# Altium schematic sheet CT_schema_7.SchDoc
size 405 x 220 mm
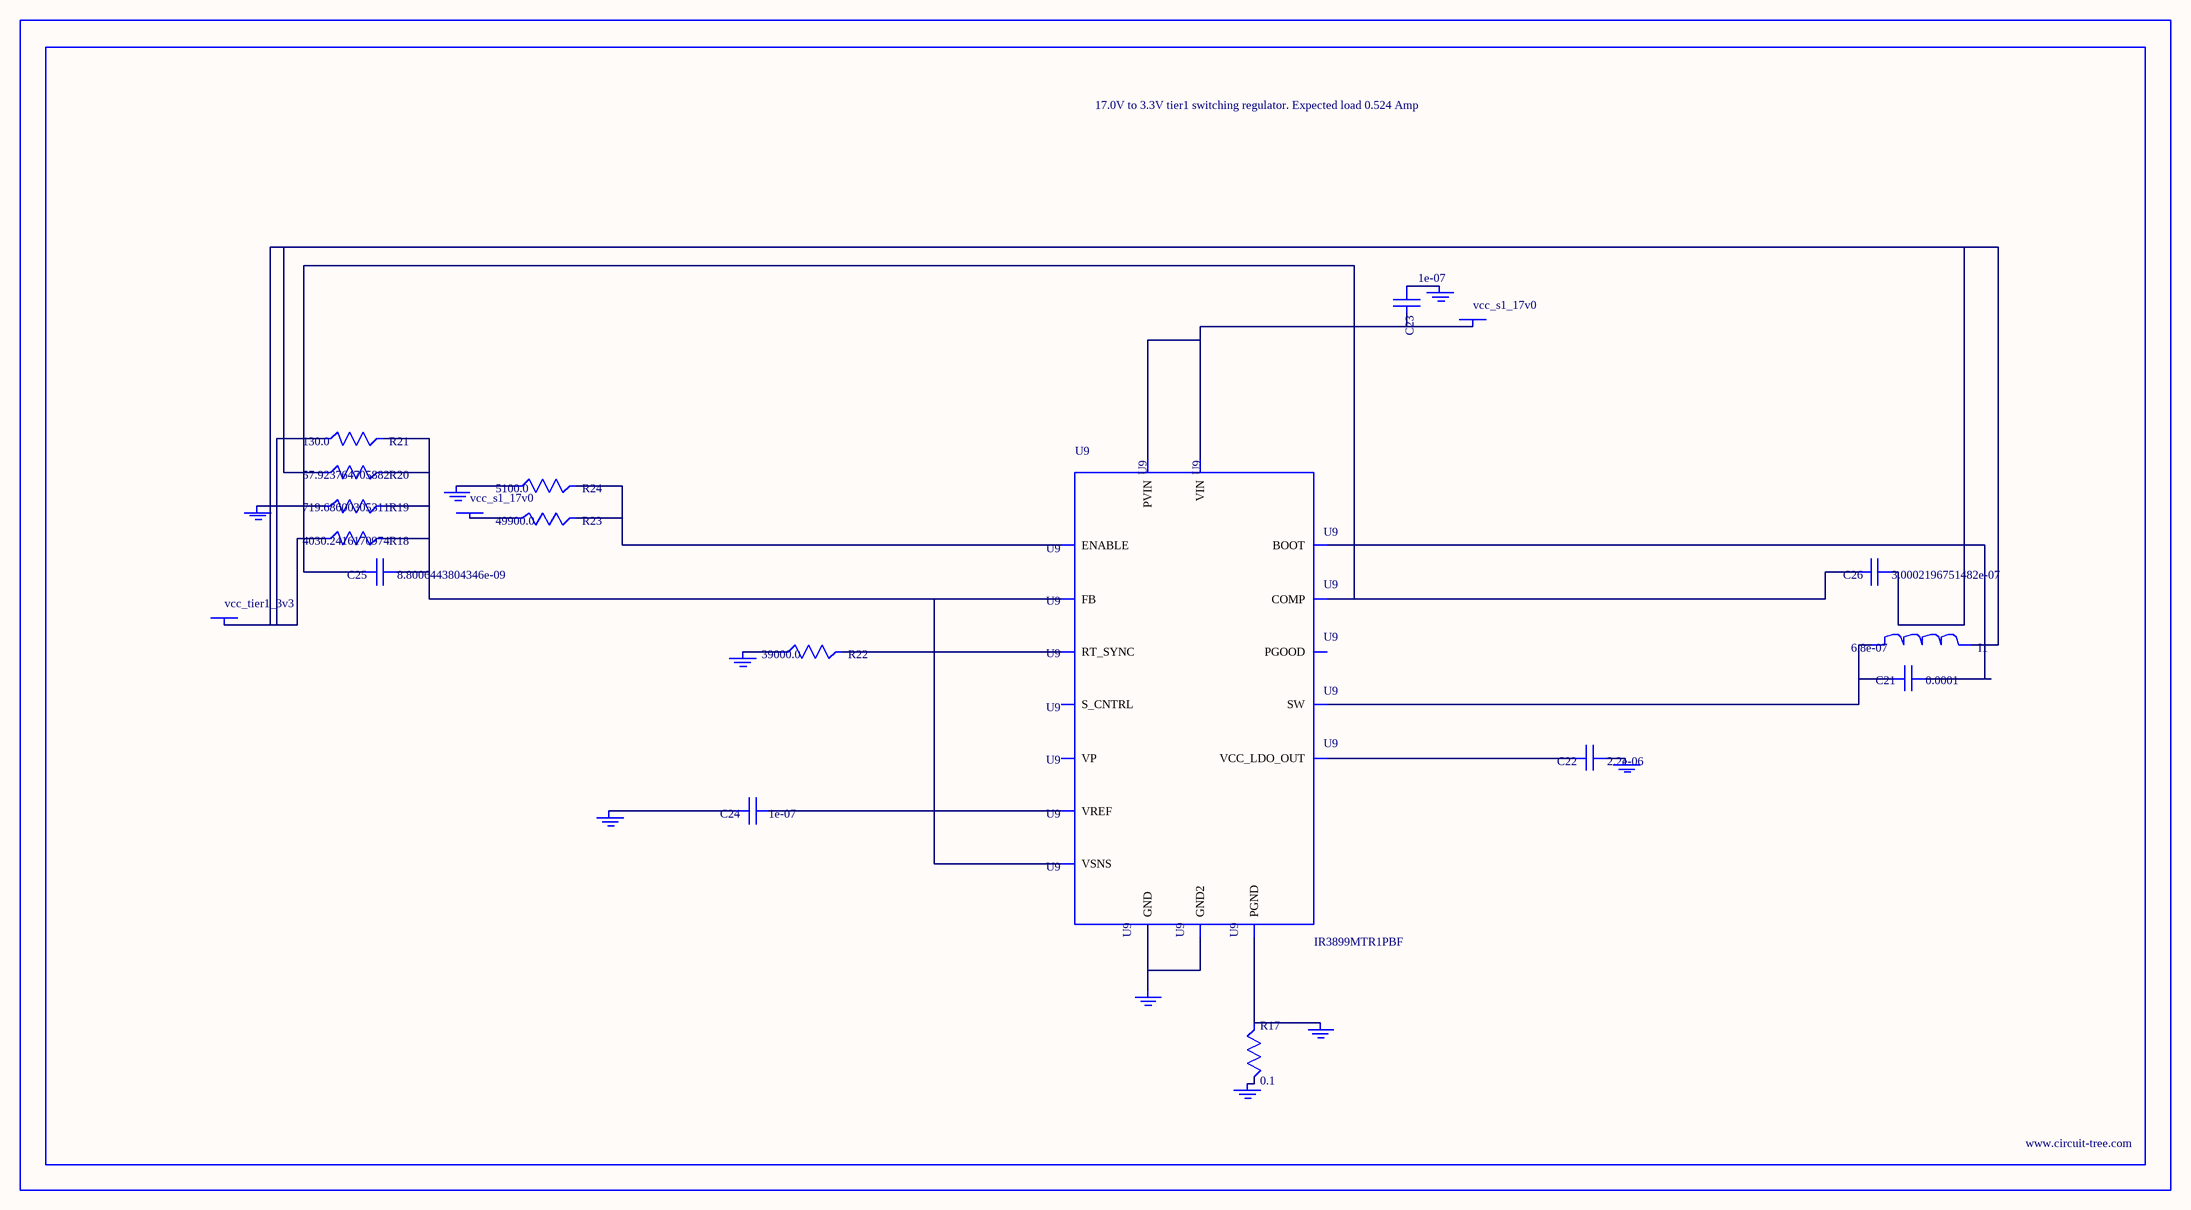
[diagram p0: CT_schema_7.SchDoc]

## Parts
BORDER6  (no value)
C21  0.0001  [C1210]
C22  2.2e-06  [C0603]
C23  1e-07  [C0402]
C24  1e-07  [C0402]
C25  8.8006443804346e-09  [R0603]
C26  3.0002196751482e-07  [R0603]
GND_INSTANCE_6_0  (no value)
GND_INSTANCE_6_1  (no value)
GND_INSTANCE_6_2  (no value)
GND_INSTANCE_6_3  (no value)
GND_INSTANCE_6_4  (no value)
GND_INSTANCE_6_5  (no value)
GND_INSTANCE_6_6  (no value)
GND_INSTANCE_6_7  (no value)
GND_INSTANCE_6_8  (no value)
I1  6.8e-07  [IND25X25CZ]
POWER_INSTANCE_6_0  vcc_s1_17v0
POWER_INSTANCE_6_1  vcc_s1_17v0
POWER_INSTANCE_6_2  vcc_tier1_3v3
R17  0.1  [R0603]
R18  4030.2416170974  [R0603]
R19  719.68600305311  [R0603]
R20  57.923764705882  [R0603]
R21  130.0  [R0603]
R22  39000.0  [R0603]
R23  49900.0  [R0603]
R24  5100.0  [R0603]
U9  IR3899MTR1PBF  [IR3899MTR1PBF]

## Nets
NetC21_1: C21.1 U9.14(BOOT)
NetC21_2: C21.2 I1.1 U9.12(SW)
NetC22_1: C22.1 GND_INSTANCE_6_4.0(GND)
NetC22_2: C22.2 U9.10(VCC_LDO_OUT)
NetC23_1: C23.1 GND_INSTANCE_6_3.0(GND)
NetC23_2: C23.2 POWER_INSTANCE_6_0.0(PWR) U9.9(VIN) U9.13(PVIN)
NetC24_1: C24.1 U9.2(VREF)
NetC24_2: C24.2 GND_INSTANCE_6_1.0(GND)
NetC25_1: C25.1 R18.2 R19.2 R20.2 R21.2 U9.1(FB) U9.8(VSNS)
NetC25_2: C25.2 C26.2 U9.3(COMP)
NetC26_1: C26.1 I1.2 POWER_INSTANCE_6_2.0(PWR) R18.1 R20.1 R21.1
NetGND_INSTANCE_6_0_0: GND_INSTANCE_6_0.0(GND) R19.1
NetGND_INSTANCE_6_2_0: GND_INSTANCE_6_2.0(GND) R22.1
NetGND_INSTANCE_6_5_0: GND_INSTANCE_6_5.0(GND) R17.2
NetGND_INSTANCE_6_6_0: GND_INSTANCE_6_6.0(GND) R17.1 U9.11(PGND)
NetGND_INSTANCE_6_7_0: GND_INSTANCE_6_7.0(GND) R24.1
NetGND_INSTANCE_6_8_0: GND_INSTANCE_6_8.0(GND) U9.4(GND) U9.17(GND2)
NetPOWER_INSTANCE_6_1_0: POWER_INSTANCE_6_1.0(PWR) R23.1
NetR22_2: R22.2 U9.5(RT_SYNC)
NetR23_2: R23.2 R24.2 U9.15(ENABLE)

Not connected (* = marked no-connect by the designer): U9 6(S_CNTRL) 7(PGOOD) 16(VP)

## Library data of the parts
BORDER6 = BORDER_PAGE6
C21 = GRM32ER61A107ME20L
C22 = C0603C225K8RACTU
C23 C24 = C0402C104K3RACTU
C25 = C25
C26 = C26
GND_INSTANCE_6_0-GND_INSTANCE_6_8 = GND
I1 = IHLP2525CZERR68M01
POWER_INSTANCE_6_0-POWER_INSTANCE_6_2 = PWR
R17 = ERJ-3RSFR10V
R18 = R18
R19 = R19
R20 = R20
R21 = RC0603JR-07130RL
R22 = RC0603JR-0739KL
R23 = RC0603FR-0749K9
R24 = RC0603JR-075K1L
